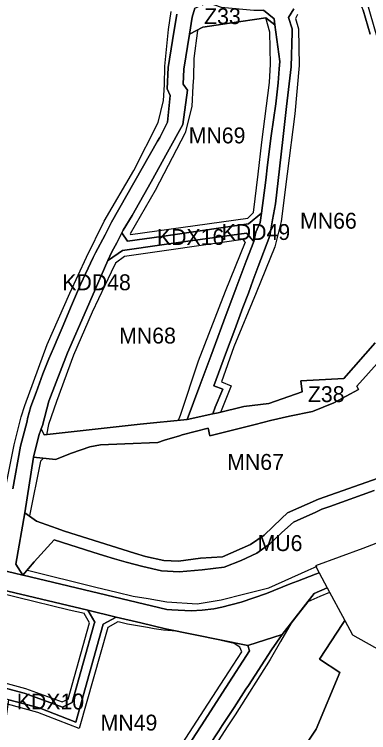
# Model space of a CAD drawing. Extents: x 7428841 to 7433518, y 5545054 to 5546840.
# Drawn here: x 7432700.7 to 7432923.5, y 5545406.8 to 5545858.6 of the extents above; entities that cross this region are included whole.
import ezdxf

# ---------------------------------------------------------------- set-up
doc = ezdxf.new("R2010")
doc.units = 0
for name, color, linetype in [('linie_rozgraniczajace', 7, 'Continuous'), ('linie_zabudowy_nieprzekraczalne', 7, 'Continuous'), ('oznaczenia_przeznaczen', 7, 'Continuous')]:
    doc.layers.add(name, color=color, linetype=linetype)

msp = doc.modelspace()

# ---------------------------------------------------------------- linework, layer by layer
at = {"layer": 'linie_rozgraniczajace'}
for points in [[(7432924.46, 5545846.25), (7432920.2, 5545861.37), (7432919.55, 5545862.9), (7432918.17, 5545865.36), (7432916.14, 5545868.05), (7432909.17, 5545870.87), (7432908.71, 5545871.05), (7432913.81, 5545872.91), (7432921.87, 5545868.65), (7432956.87, 5545747.44)], [(7432814.2, 5545862.45), (7432812.61, 5545856.87), (7432810.88, 5545846.1), (7432807.37, 5545824.23), (7432806.97, 5545814.77), (7432809.62, 5545811.05), (7432806.64, 5545789.25), (7432796.98, 5545772.01), (7432786.74, 5545753.36), (7432774.79, 5545732.08), (7432769.21, 5545722.79), (7432768.41, 5545721.26), (7432765.14, 5545714.95), (7432761.98, 5545709.24), (7432759.58, 5545703.8), (7432746.07, 5545672.99), (7432734.24, 5545645.69), (7432722.45, 5545615.28), (7432718.36, 5545600.07), (7432717.59, 5545597.9), (7432716.11, 5545593.74), (7432712.75, 5545580.07), (7432707.3, 5545545.07), (7432701.65, 5545512.85), (7432706.04, 5545505.84), (7432684.8, 5545510.91)], [(7432876.5, 5545862.17), (7432873.21, 5545856.56), (7432875.35, 5545849.57), (7432875.51, 5545848.62), (7432875.48, 5545847.44), (7432874.73, 5545825.63), (7432871.83, 5545800.73), (7432869.74, 5545781.77), (7432867.48, 5545761.53), (7432864.92, 5545739.45), (7432863.14, 5545729.41), (7432861.35, 5545719.36), (7432854.16, 5545700.06), (7432851.02, 5545691.64), (7432847.89, 5545683.22), (7432844.51, 5545674.14), (7432841.13, 5545665.06), (7432839.47, 5545660.32), (7432833.61, 5545644.86), (7432826.2, 5545624.99), (7432831.78, 5545622.78), (7432827.07, 5545611.48), (7432825.56, 5545607.28), (7432809.48, 5545603.78), (7432817.31, 5545625.16), (7432824.21, 5545643.58), (7432827.19, 5545651.64), (7432832.43, 5545665.8), (7432840.2, 5545686.7), (7432846.46, 5545703.29), (7432851.26, 5545715.65), (7432852.6, 5545721.71), (7432855.41, 5545727.78), (7432856.1, 5545733.47), (7432858.81, 5545754.33), (7432859.98, 5545763.97), (7432862.22, 5545782.3), (7432865.22, 5545802.39), (7432866.72, 5545815.52), (7432867.33, 5545824.32), (7432867.69, 5545828.9), (7432864.64, 5545852.13), (7432864.1, 5545855.86), (7432857.39, 5545861.33)], [(7432927.6, 5545652.07), (7432907.88, 5545629.63), (7432880.98, 5545628.02), (7432881.64, 5545621.18), (7432860.76, 5545613.93), (7432845.08, 5545612.01), (7432828.89, 5545608), (7432825.56, 5545607.28), (7432827.07, 5545611.48), (7432831.78, 5545622.78), (7432826.2, 5545624.99), (7432833.61, 5545644.86), (7432839.47, 5545660.32), (7432841.13, 5545665.06), (7432844.51, 5545674.14), (7432847.89, 5545683.22), (7432851.02, 5545691.64), (7432854.16, 5545700.06), (7432861.35, 5545719.36), (7432863.14, 5545729.41), (7432864.92, 5545739.45), (7432867.48, 5545761.53), (7432869.74, 5545781.77), (7432871.83, 5545800.73), (7432874.73, 5545825.63), (7432875.48, 5545847.44), (7432875.51, 5545848.62), (7432875.35, 5545849.57), (7432873.21, 5545856.56), (7432876.5, 5545862.17)], [(7432920.2, 5545861.37), (7432924.46, 5545846.25)], [(7432802.96, 5545858.8), (7432800.11, 5545842.14), (7432797.4, 5545825.23), (7432796.84, 5545811.76), (7432798.77, 5545807.52), (7432796.97, 5545790.86), (7432792.99, 5545782.81), (7432792.22, 5545781.2), (7432790.8, 5545778.9), (7432761.91, 5545727.97), (7432757.78, 5545720.03), (7432751.8, 5545708.57), (7432750.23, 5545705.68), (7432742.37, 5545688.63), (7432736.04, 5545673.96), (7432731.42, 5545662.92), (7432728.29, 5545655.58), (7432725.32, 5545648.73), (7432722.35, 5545641.89), (7432718.62, 5545632.58), (7432714.45, 5545620.82), (7432711.17, 5545611.96), (7432709.08, 5545604.51), (7432708.71, 5545602.71), (7432704.49, 5545587.01), (7432699.79, 5545560.16)], [(7432699.79, 5545560.16), (7432704.49, 5545587.01), (7432708.71, 5545602.71), (7432709.08, 5545604.51), (7432711.17, 5545611.96), (7432714.45, 5545620.82), (7432718.62, 5545632.58), (7432722.35, 5545641.89), (7432725.32, 5545648.73), (7432728.29, 5545655.58), (7432731.42, 5545662.92), (7432736.04, 5545673.96), (7432742.37, 5545688.63), (7432750.23, 5545705.68), (7432751.8, 5545708.57), (7432757.78, 5545720.03), (7432761.91, 5545727.97), (7432790.8, 5545778.9), (7432792.22, 5545781.2), (7432792.99, 5545782.81), (7432796.97, 5545790.86), (7432798.77, 5545807.52), (7432796.84, 5545811.76), (7432797.4, 5545825.23), (7432800.11, 5545842.14), (7432802.96, 5545858.8)], [(7432929.57, 5545566.82), (7432892.02, 5545553.66), (7432872.52, 5545545.09), (7432868.67, 5545541.53), (7432857.82, 5545531.08), (7432849.17, 5545525.21), (7432831.55, 5545517.34), (7432817.83, 5545516.65), (7432803.89, 5545514.61), (7432794.63, 5545515.05), (7432783.19, 5545517.61), (7432776.19, 5545519.69), (7432732.25, 5545533.51), (7432727, 5545535.4), (7432724.6, 5545536.26), (7432724.09, 5545536.44), (7432714.56, 5545539.86), (7432707.3, 5545545.07), (7432712.75, 5545580.07), (7432726.59, 5545578.54), (7432736.6, 5545582.63), (7432748.24, 5545586.68), (7432754.96, 5545587.86), (7432770.16, 5545588.46), (7432790.87, 5545589.36), (7432795.13, 5545590.83), (7432804.55, 5545593.53), (7432806.23, 5545594.18), (7432822.71, 5545598.38), (7432823.57, 5545593.42), (7432837.84, 5545597.05), (7432852.1, 5545600.67), (7432861.85, 5545603.1), (7432873.85, 5545605.92), (7432888.25, 5545608.86), (7432901.72, 5545614.28), (7432917.15, 5545622.69), (7432916.18, 5545624.85), (7432938.12, 5545649.21)], [(7432938.12, 5545649.21), (7432916.18, 5545624.85), (7432917.15, 5545622.69), (7432901.72, 5545614.28), (7432888.25, 5545608.86), (7432873.85, 5545605.92), (7432861.85, 5545603.1), (7432852.1, 5545600.67), (7432837.84, 5545597.05), (7432823.57, 5545593.42), (7432822.71, 5545598.38), (7432806.23, 5545594.18), (7432804.55, 5545593.53), (7432795.13, 5545590.83), (7432790.87, 5545589.36), (7432770.16, 5545588.46), (7432754.96, 5545587.86), (7432748.24, 5545586.68), (7432736.6, 5545582.63), (7432726.59, 5545578.54), (7432712.75, 5545580.07), (7432716.11, 5545593.74), (7432717.59, 5545597.9), (7432719.42, 5545594.12), (7432779.91, 5545600.79), (7432809.48, 5545603.78), (7432825.56, 5545607.28), (7432828.89, 5545608), (7432845.08, 5545612.01), (7432860.76, 5545613.93), (7432881.64, 5545621.18), (7432880.98, 5545628.02), (7432907.88, 5545629.63), (7432927.6, 5545652.07)], [(7432701.65, 5545512.85), (7432707.3, 5545545.07), (7432714.56, 5545539.86), (7432724.09, 5545536.44), (7432724.6, 5545536.26), (7432727, 5545535.4), (7432732.25, 5545533.51), (7432776.19, 5545519.69), (7432783.19, 5545517.61), (7432794.63, 5545515.05), (7432803.89, 5545514.61), (7432817.83, 5545516.65), (7432831.55, 5545517.34), (7432849.17, 5545525.21), (7432857.82, 5545531.08), (7432868.67, 5545541.53), (7432872.52, 5545545.09), (7432892.02, 5545553.66), (7432929.57, 5545566.82)], [(7432927.07, 5545559.08), (7432899.11, 5545549.06), (7432894.16, 5545547.3), (7432889.82, 5545545.37), (7432880.86, 5545541.33), (7432876.24, 5545539.23), (7432868.97, 5545532.76), (7432865.2, 5545529.23), (7432861.41, 5545525.66), (7432853.2, 5545519.68), (7432843.34, 5545515.11), (7432832.7, 5545510.85), (7432818.85, 5545509.29), (7432804.3, 5545507.93), (7432793.31, 5545508.62), (7432781.62, 5545511.23), (7432771.03, 5545514.1), (7432763.67, 5545516.19), (7432756.87, 5545518.25), (7432750.07, 5545520.32), (7432725.77, 5545528.13), (7432713.23, 5545514.32), (7432706.04, 5545505.84), (7432701.65, 5545512.85)], [(7432941.79, 5545531.05), (7432919.93, 5545522.54), (7432890.03, 5545511.68), (7432892.38, 5545507.34), (7432890.13, 5545506.49), (7432878.72, 5545502.14), (7432874.16, 5545500.35), (7432859.33, 5545494.39), (7432851.32, 5545491.6), (7432843.31, 5545488.81), (7432831.11, 5545485.78), (7432826.13, 5545484.74), (7432818.83, 5545483.89), (7432811.9, 5545483.44), (7432799.67, 5545484.11), (7432796.57, 5545484.28), (7432706.24, 5545505.79), (7432706.04, 5545505.84), (7432713.23, 5545514.32), (7432725.77, 5545528.13), (7432750.07, 5545520.32), (7432756.87, 5545518.25), (7432763.67, 5545516.19), (7432771.03, 5545514.1), (7432781.62, 5545511.23), (7432793.31, 5545508.62), (7432804.3, 5545507.93), (7432818.85, 5545509.29), (7432832.7, 5545510.85), (7432843.34, 5545515.11), (7432853.2, 5545519.68), (7432861.41, 5545525.66), (7432865.2, 5545529.23), (7432868.97, 5545532.76), (7432876.24, 5545539.23), (7432880.86, 5545541.33), (7432889.82, 5545545.37), (7432894.16, 5545547.3), (7432899.11, 5545549.06), (7432927.07, 5545559.08)], [(7432684.8, 5545510.91), (7432706.04, 5545505.84), (7432706.24, 5545505.79), (7432796.57, 5545484.28), (7432799.67, 5545484.11), (7432811.9, 5545483.44), (7432818.83, 5545483.89), (7432826.13, 5545484.74), (7432831.11, 5545485.78), (7432843.31, 5545488.81), (7432851.32, 5545491.6), (7432859.33, 5545494.39), (7432874.16, 5545500.35), (7432878.72, 5545502.14), (7432890.13, 5545506.49), (7432892.38, 5545507.34), (7432897.49, 5545497.9), (7432889.23, 5545494.22), (7432869.12, 5545468.44), (7432847.64, 5545461.54), (7432795.86, 5545472.08), (7432780.35, 5545475.78), (7432764.84, 5545479.48), (7432747.03, 5545483.73), (7432662.85, 5545503.81)], [(7432823.32, 5545398.63), (7432829.4, 5545407.97), (7432831.49, 5545411.21), (7432838.9, 5545422.71), (7432846.32, 5545434.21), (7432847.89, 5545436.52), (7432862.53, 5545458.84), (7432869.12, 5545468.44), (7432889.23, 5545494.22), (7432897.49, 5545497.9), (7432908.61, 5545477.37), (7432907.38, 5545475.46), (7432892.73, 5545453.04), (7432905.46, 5545444.64), (7432890.49, 5545408.89), (7432884.23, 5545399.51)], [(7432691.97, 5545390.71), (7432697.15, 5545427.52), (7432716.32, 5545422.39), (7432739.46, 5545413.31), (7432747.98, 5545444.14), (7432756.49, 5545474.97), (7432764.84, 5545479.48), (7432780.35, 5545475.78), (7432795.86, 5545472.08), (7432847.64, 5545461.54), (7432848.64, 5545458.32), (7432833.76, 5545435.16), (7432818.19, 5545411.13), (7432812.33, 5545402.01)], [(7432884.23, 5545399.51), (7432890.49, 5545408.89), (7432905.46, 5545444.64), (7432892.73, 5545453.04), (7432907.38, 5545475.46), (7432908.61, 5545477.37), (7432913.46, 5545468.42), (7433024.89, 5545405.88)], [(7432812.33, 5545402.01), (7432818.19, 5545411.13), (7432833.76, 5545435.16), (7432848.64, 5545458.32), (7432847.64, 5545461.54), (7432869.12, 5545468.44), (7432862.53, 5545458.84), (7432847.89, 5545436.52), (7432846.32, 5545434.21), (7432838.9, 5545422.71), (7432831.49, 5545411.21), (7432829.4, 5545407.97), (7432823.32, 5545398.63)]]:
    msp.add_lwpolyline(points, dxfattribs=at)
for points in [[(7432810.88, 5545846.1), (7432812.61, 5545856.87), (7432814.2, 5545862.45), (7432822.35, 5545866.09), (7432830.78, 5545863.26), (7432851.27, 5545861.31), (7432857.39, 5545861.33), (7432864.1, 5545855.86), (7432864.64, 5545852.13), (7432858.88, 5545856.47), (7432836.13, 5545853.1), (7432819.32, 5545850.62)], [(7432768.41, 5545721.26), (7432769.21, 5545722.79), (7432774.79, 5545732.08), (7432786.74, 5545753.36), (7432796.98, 5545772.01), (7432806.64, 5545789.25), (7432809.62, 5545811.05), (7432806.97, 5545814.77), (7432807.37, 5545824.23), (7432810.88, 5545846.1), (7432819.32, 5545850.62), (7432836.13, 5545853.1), (7432858.88, 5545856.47), (7432864.64, 5545852.13), (7432867.69, 5545828.9), (7432867.33, 5545824.32), (7432866.72, 5545815.52), (7432865.22, 5545802.39), (7432862.22, 5545782.3), (7432859.98, 5545763.97), (7432858.81, 5545754.33), (7432856.1, 5545733.47), (7432847.98, 5545726.76), (7432840.55, 5545725.73), (7432819.05, 5545722.71), (7432793.24, 5545718.99), (7432771.87, 5545715.92)], [(7432759.58, 5545703.8), (7432761.98, 5545709.24), (7432765.14, 5545714.95), (7432768.41, 5545721.26), (7432771.87, 5545715.92), (7432793.24, 5545718.99), (7432819.05, 5545722.71), (7432840.55, 5545725.73), (7432847.98, 5545726.76), (7432856.1, 5545733.47), (7432855.41, 5545727.78), (7432852.6, 5545721.71), (7432851.26, 5545715.65), (7432846.68, 5545720.9), (7432808.36, 5545715.66), (7432793.45, 5545713.59), (7432768.72, 5545710.18), (7432759.97, 5545704.05)], [(7432717.59, 5545597.9), (7432718.36, 5545600.07), (7432722.45, 5545615.28), (7432734.24, 5545645.69), (7432746.07, 5545672.99), (7432759.58, 5545703.8), (7432759.97, 5545704.05), (7432768.72, 5545710.18), (7432793.45, 5545713.59), (7432808.36, 5545715.66), (7432846.68, 5545720.9), (7432851.26, 5545715.65), (7432846.46, 5545703.29), (7432840.2, 5545686.7), (7432832.43, 5545665.8), (7432827.19, 5545651.64), (7432824.21, 5545643.58), (7432817.31, 5545625.16), (7432809.48, 5545603.78), (7432779.91, 5545600.79), (7432719.42, 5545594.12)], [(7432600.07, 5545462.99), (7432609.36, 5545485.76), (7432618.66, 5545508.52), (7432626.69, 5545512.44), (7432662.85, 5545503.81), (7432747.03, 5545483.73), (7432751.3, 5545476.36), (7432750.98, 5545475.2), (7432737.03, 5545425.73), (7432731, 5545422.9), (7432721.44, 5545426.38), (7432706.79, 5545431.71), (7432693.5, 5545435.26), (7432677.64, 5545439.51), (7432638.64, 5545447.5), (7432602.92, 5545457.15)], [(7432676.32, 5545432.5), (7432677.64, 5545439.51), (7432693.5, 5545435.26), (7432706.79, 5545431.71), (7432721.44, 5545426.38), (7432731, 5545422.9), (7432737.03, 5545425.73), (7432750.98, 5545475.2), (7432751.3, 5545476.36), (7432747.03, 5545483.73), (7432764.84, 5545479.48), (7432756.49, 5545474.97), (7432747.98, 5545444.14), (7432739.46, 5545413.31), (7432716.32, 5545422.39), (7432697.15, 5545427.52)]]:
    msp.add_lwpolyline(points, close=True, dxfattribs=at)
at = {"layer": 'linie_zabudowy_nieprzekraczalne'}
for points in [[(7432695.36, 5545561.62), (7432700.58, 5545587.88), (7432704.91, 5545605.53), (7432707.27, 5545612.64), (7432721.28, 5545651), (7432735.53, 5545683.2), (7432746.17, 5545705.98), (7432757.15, 5545728.45), (7432775.79, 5545760.35), (7432791.15, 5545790.68), (7432794.62, 5545804.39), (7432795.08, 5545814.24), (7432795.4, 5545826.14), (7432797.74, 5545849.15), (7432799.24, 5545860.38)], [(7432878.76, 5545858.6), (7432877.54, 5545856.04), (7432879.45, 5545849.62), (7432879.8, 5545826.37), (7432877.07, 5545796), (7432872.26, 5545758.34), (7432868.48, 5545728.38), (7432864.46, 5545712.38), (7432852.75, 5545683.49), (7432838.66, 5545649.4), (7432831, 5545627.39)], [(7432851.22, 5545733.93), (7432854.07, 5545758.05), (7432856.28, 5545778.21), (7432861.17, 5545815.84), (7432861.83, 5545827.4), (7432861.32, 5545847.38), (7432858.88, 5545856.47)], [(7432815.98, 5545848.58), (7432813.55, 5545830.87), (7432813.37, 5545819.02), (7432813.07, 5545813.68), (7432812.27, 5545800.72), (7432808.07, 5545784.19), (7432789.35, 5545747.85), (7432773.59, 5545720.59)], [(7432773.57, 5545720.6), (7432773.83, 5545720.23), (7432847.5, 5545730.41), (7432851.22, 5545733.93)], [(7432845.98, 5545715.52), (7432844.68, 5545716.92), (7432770.02, 5545706.4), (7432764.25, 5545702.18)], [(7432803.97, 5545603.27), (7432805.19, 5545606.46), (7432816.55, 5545640.63), (7432833.6, 5545684.41), (7432845.99, 5545715.56)], [(7432764.25, 5545702.18), (7432761.65, 5545696.48), (7432749.73, 5545671.38), (7432737.94, 5545644.17), (7432727.27, 5545615.19), (7432722.25, 5545600.64), (7432720.92, 5545594.21)], [(7432831, 5545627.39), (7432837, 5545625.03), (7432830.27, 5545608.27)], [(7432717.07, 5545577.66), (7432710.14, 5545543.16)], [(7432718.84, 5545579.25), (7432717.07, 5545577.66)], [(7432627.52, 5545509.5), (7432621.01, 5545506.32), (7432603.35, 5545463.1), (7432605.02, 5545459.69), (7432639.33, 5545450.42), (7432678.33, 5545442.43), (7432707.69, 5545434.57), (7432730.86, 5545426.14), (7432734.51, 5545427.86), (7432748.06, 5545475.97), (7432744.71, 5545481.75)], [(7432744.8, 5545481.71), (7432735.26, 5545483.88), (7432702.59, 5545491.87), (7432686.72, 5545495.72), (7432627.57, 5545509.48), (7432627.57, 5545509.48)], [(7432708.92, 5545508.92), (7432708.92, 5545508.92), (7432752.03, 5545498.34), (7432765.18, 5545495.16), (7432775.44, 5545492.65), (7432784.85, 5545491.07), (7432796.63, 5545489.1), (7432815.77, 5545487.9), (7432830.76, 5545490.35), (7432845.73, 5545494.07), (7432860.7, 5545497.8), (7432885.56, 5545509.03), (7432891.24, 5545511.54)], [(7432899.03, 5545495.05), (7432892.82, 5545492.44), (7432885.29, 5545489), (7432879.18, 5545481.33), (7432874.84, 5545475.72), (7432868.11, 5545464.09)], [(7432765.84, 5545476.46), (7432759.48, 5545472.93), (7432741.45, 5545409.31), (7432715.38, 5545419.53), (7432696.42, 5545424.61), (7432656.1, 5545434.16), (7432636.52, 5545438.75), (7432594.82, 5545449.99), (7432586.37, 5545450.84), (7432585.72, 5545452.18)], [(7432843.74, 5545457.64), (7432842.63, 5545460.5), (7432838.92, 5545462.84), (7432821.75, 5545466.81), (7432802.76, 5545470.66), (7432802.76, 5545470.66), (7432794.57, 5545471.19), (7432788.55, 5545472.19), (7432784.43, 5545472.89), (7432771.81, 5545475.01), (7432766.87, 5545476.2), (7432765.84, 5545476.46)], [(7432868.11, 5545464.09), (7432861.59, 5545452.76), (7432839.5, 5545418.06), (7432834.55, 5545410.53), (7432807.19, 5545367.66), (7432785.78, 5545335.05), (7432773.39, 5545316.35), (7432764.17, 5545301.67), (7432752.49, 5545283.47), (7432742.82, 5545268.39), (7432726.52, 5545243.78), (7432718.77, 5545232.19), (7432718.77, 5545232.19)], [(7432613.18, 5545080.26), (7432629.5, 5545108.9), (7432645.5, 5545137.17), (7432650.14, 5545144.69), (7432660.47, 5545164.33), (7432677.75, 5545196.19), (7432684.65, 5545209.15), (7432690.98, 5545220.65), (7432696.69, 5545231.27), (7432711.59, 5545253.6), (7432744.32, 5545303.58), (7432758.27, 5545326.12), (7432771.21, 5545345.61), (7432820.13, 5545421.04), (7432835.52, 5545445.02), (7432843.74, 5545457.64)]]:
    msp.add_lwpolyline(points, dxfattribs=at)

# ---------------------------------------------------------------- texts
at = {"layer": 'oznaczenia_przeznaczen'}
for s, p in [('Z33', (7432820.06, 5545852.49)), ('MN69', (7432810.38, 5545777.48)), ('MN66', (7432880.41, 5545723.81)), ('KDD49', (7432831.07, 5545716.71)), ('KDX16', (7432790.38, 5545713.59)), ('KDD48', (7432730.85, 5545685.08)), ('MN68', (7432766.63, 5545651.56)), ('Z38', (7432885.35, 5545614.73)), ('MN67', (7432834.58, 5545572.09)), ('MU6', (7432853.68, 5545521.02)), ('KDX10', (7432702.23, 5545421.38)), ('MN49', (7432754.97, 5545408.1))]:
    msp.add_text(s, height=10, dxfattribs=at).set_placement(p)

doc.saveas('drawing.dxf')
